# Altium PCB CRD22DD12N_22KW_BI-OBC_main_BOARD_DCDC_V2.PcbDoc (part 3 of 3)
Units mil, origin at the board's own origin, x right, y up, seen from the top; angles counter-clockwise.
Board outline 9308.07 x 7086.6 mil, 4 copper layers (TOP, GND02, POWER03, BOTTOM), stack 74.3 mil thick; 339 components, 177 nets, 874 pads, 199 vias.
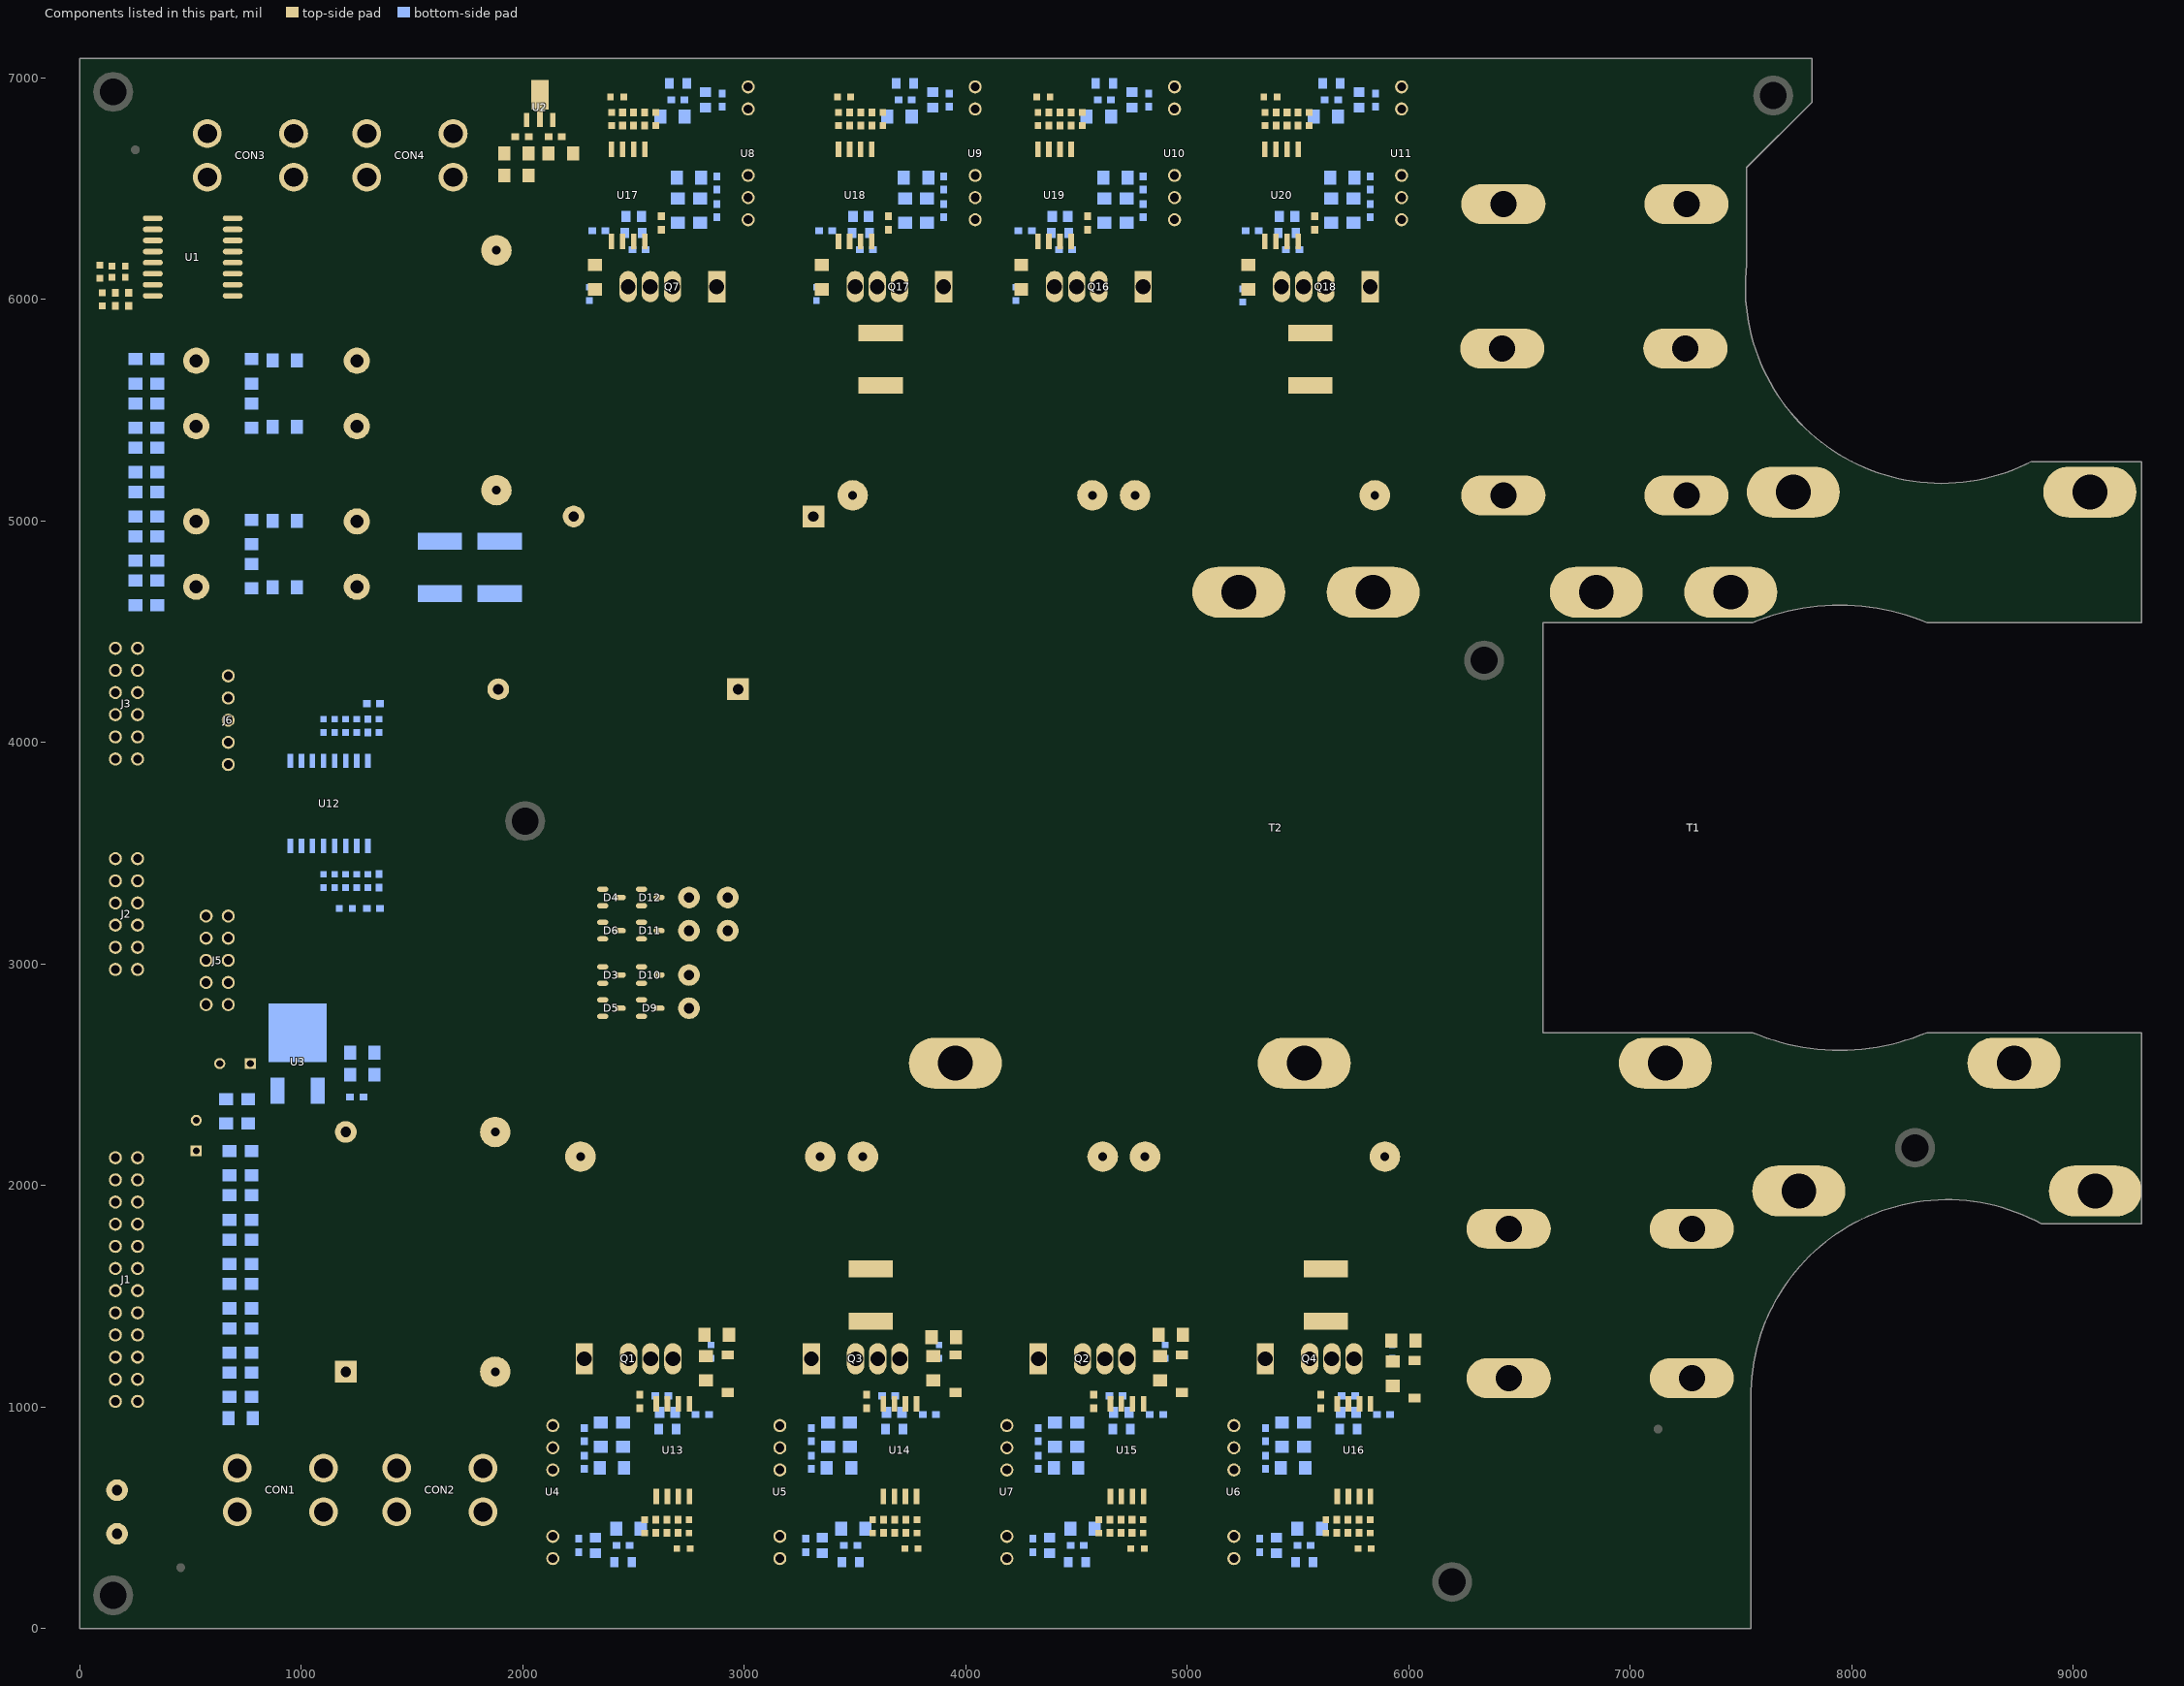
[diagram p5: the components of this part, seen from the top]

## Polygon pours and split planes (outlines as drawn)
DCINPUT on TOP "DCINPUT_L01_P003" (solid, pour order 3): 5960,2265 6035,2185 6032.5,2020 5885,1872.5 5885,1645 5830,1590 5345,1590 5220,1465 5135,1465 5080,1520 4765,1520 4710,1465 4425,1465 4395,1435 4395,1180 4345,1130 4250,1130 4220,1160 4220,1430 4140,1510 3860,1510 3780,1590 3350,1590 3225,1465 3080,1465 3010,1535 2730,1535 2660,1465 2395,1465 2345,1415 2345,1185 2300,1140 1985,1140 1795,950 1360,950 1200,790 1200,460 1185,445 655,445 635,465 635,765 695,825 695,1625 925,1855 2300,1855 2710,2265
VO+ on TOP "VO+_L01_P000" (solid, pour order 0): 1530,5516.28 1386.28,5660 470,5660 460,5670 460,5775 480,5795 600,5795 635,5830 635,5955 645,5965 725,5965 725,5985 645,5985 630,6000 630,6170 640,6180 1609.14,6180.86 1980,5810 2755,5810 2820,5875 2820,6130 2840,6150 2935,6150 2945,6140 2945,5900 3015,5830 3250,5830 3440,5640 3775,5640 3940,5805 4700,5805 4735,5840 4735,6135 4750,6150 4870,6150 4880,6140 4880,5880 4910,5850 5160,5850 5375,5635 5830,5635 5905,5560 5905,5060 5845,4997.5 5045,4995 4915,4865 3780,4870 1785,4865 1530,5120
SGND on GND02 "SGND_L02_P007" (solid, pour order 7): 6044.69,7005.25 6044.69,6714.69 5835,6505 5140,6505 5050,6595 5050,6634.74 4999.86,6684.88 4690.71,6684.88 4620,6614.17 4620,6565 4555,6500 4200,6500 4145,6555 4145,6633.28 4083.87,6694.41 3741.96,6694.41 3680,6632.46 3680,6540 3640,6500 3220,6500 3105,6615 2705,6615 2595,6505 2030,6505 2020,6515 2020,6857.62 1982.63,6894.99 442.54,6894.99 330,6782.46 330,4766 666.59,4429.41 1367.3,4429.41 1404.41,4392.3 1404.41,3757.7 1367.3,3720.59 50.47,3720.71 50.47,7036.01 6013.92,7036.01
AGND on GND02 "AGND_L02_P004" (solid, pour order 4): 52,3680 1366.72,3680 1404.41,3642.3 1404.41,2435.24 1290.67,2321.5 619.04,2321.5 355,2057.46 355,493.34 543.34,305 2007.46,305 2070,367.54 2070,490.89 2234.12,655 2475,655 2514.41,694.41 2514.41,759.41 2545,790 2975,790 3005,760 3005,641.98 3041.86,605.12 3458.19,605.12 3569.85,716.78 3569.85,754.85 3600,785 4076.27,785 4111.27,750 4111.27,691.42 4129.1,673.59 4538.59,673.59 4565,700 4565,750 4603.36,788.36 5006.64,788.36 5045,750 5045,602.54 5117.52,530.02 5482.72,530.02 5570,617.3 5570,760 5600,790 5940,790 5969.41,760.59 5969.41,69.42 5950,50 50,50 50,3677.99
PGND on GND02 "PGND_L02_P006" (solid, pour order 6): 628.41,2271.41 1306.04,2271.41 1354.04,2319.41 4979.41,2319.41 4980,2320 5160,2140 5675,2140 5969.95,1845.05 5969.95,855.05 5949.14,834.14 5555.86,834.14 5530,808.28 5530,634.11 5465.89,570 5125,570 5041.65,662.46 5041.65,1358.35 5020,1380 4820,1380 4790,1350 4235,1350 4215,1330 4215,1115 4102.5,1002.5 4102.5,852.5 4080,830 3580,830 3530,780 3530,734.11 3440.89,645 3058.61,645 3045.09,658.51 3045.09,808.19 3014.14,839.14 3014.14,1330.86 2960,1385 2730,1385 2685,1340 2180,1340 2125,1285 2125,1070 2030.59,975.59 2030.59,384.7 1990.89,345 555,345 395.03,504.97 395.03,2037.81 629.06,2271.85
SPGND on GND02 "SPGND_L02_P005" (solid, pour order 5): 774.83,5980 1210,6415.17 1210,6779.17 1235.83,6805 1236.41,6804.41 1905.59,6804.41 1950.59,6759.41 1950.59,6339.41 1951.41,6339.41 2360.83,5930 2361.14,5930.31 3105.31,5930.31 3217.5,6042.5 3217.5,6420 3242.5,6445 3731.91,6445 3772.5,6404.41 3772.5,5957.5 3799.41,5930.59 4880.59,5930.59 5150,6200 5150,6345 5255,6450 5600,6450 5700.41,6349.59 5700.41,5949.14 5770,5879.56 5770,5220.1 5514.32,4964.41 3609.41,4964.41 2880,4235 2881.75,4233.25 2881.75,4186.75 2881.24,4186.75 2869.49,4175 1600.83,4175 1515,4260.83 1515,4425 1470,4470 684,4470 370.59,4783.41 370.59,5870.59 480,5980
LEGB on POWER03 "LEGB_L03_P011" (solid, pour order 11): 4483.52,1143.35 4483.52,1753.52 4595,1865 4930,1865 4985,1920 5290,1920 5339.99,1870.01 6549.99,1870.01 6620,1800 6620,1100 6580.59,1060.59 6165.24,1060.59 6140,1085.83 6140,1284.17 6059.17,1365 5440.83,1365 5405,1329.17 5405,1140.83 5394.17,1130 5290,1130 5270.59,1149.41 5270.59,1278.9 5204.52,1344.97 4605.8,1344.97 4570,1309.17 4570,1150.83 4554.17,1135 4490.83,1135
DCINPUT on POWER03 "DCINPUT_L03_P010" (solid, pour order 10): 660.59,1315.59 1770,2425 3060,2425 3245,2240 4005,2240 4377.5,1867.5 4377.5,1145 4342.5,1110 4125,1110 4055,1180 4055,1350 4015,1390 2425,1390 2354.41,1319.41 2354.41,1147.41 2297,1090 1395,1090 1175,870 1175,510 1135,470 675.83,470 660,485.83 660,1314.17
SLEGA on POWER03 "SLEGA_L03_P009" (solid, pour order 9): 2724.17,6155 2735.59,6143.59 2735.59,5954.41 2835,5855 2975,5855 3080,5960 3270,5960 3375,5855 3755,5855 3825,5925 3825,6144.17 3840.83,6160 3974.17,6160 4000.59,6133.59 4000.59,5929.41 4075,5855 4875,5855 4975,5955 5195,5955 5295,5855 6015,5855 6240,6080 6240,6490 6285,6535 6544.56,6535 6585,6494.56 6585,5100 6535,5050 6270,5050 6035,5285 5425,5285 5340,5200 4955,5200 4870,5285 3390,5285 3300,5195 2815,5195 2635.59,5374.41 2635.59,6135.59 2654.41,6154.41
VO+ on POWER03 "VO+_L03_P008" (solid, pour order 8): 405,5775 457.5,5827.5 2080,5827.5 2165,5742.5 2165,5085 2070,4990 1475,4990 1365,5100 450,5100 405,5145
LEGA on BOTTOM "LEGA_L04_P014" (solid, pour order 14): 4200,2629.17 4159.17,2670 3125,2670 2690,2235 2690,1995 2430,1735 2430,1160.83 2445.83,1145 2499.17,1145 2515.59,1161.41 2515.59,1385.59 2625,1495 2880,1495 2910,1465 2980,1465 3137.49,1307.51 3137.49,1192.51 3204.41,1125.59 3325.59,1125.59 3350,1150 3350,1369.17 3498.33,1517.5 4142.5,1517.5 4200,1575
SLEGB on BOTTOM "SLEGB_L04_P013" (solid, pour order 13): 4220.59,5310.59 4490.2,5580.2 4490.2,5889.8 4560.59,5960.19 4560.59,6120.59 4579.41,6139.41 4640.59,6139.41 4655.59,6124.41 4655.59,5924.41 4753.15,5826.85 4896.47,5826.85 4952.12,5882.5 5089.17,5882.5 5196.09,5775.59 5665.59,5775.59 5755,5865 5755,6124.17 5770.47,6139.64 5940.32,6139.64 5959.88,6120.08 5959.88,5625.14 5610.59,5275.85 5610.59,4869.41 5660.19,4819.81 5995.02,4819.81 6029.88,4784.95 6029.88,4570.14 6009.74,4550 4655,4550 4220.01,4984.99 4220.01,5309.35
VO+ on BOTTOM "VO+_L04_P012" (solid, pour order 12): 485.83,5980 645,5980 790,6125 1025,6125 1170,5980 2050,5980 2260,5770 2610,5770 2660,5820 2766.42,5820 2819.64,5873.22 2819.64,6139.61 2839.61,6159.59 2954.59,6159.59 2970,6144.17 2970,5870.38 2985.31,5855.07 3189.93,5855.07 3270,5775 3540,5775 3635,5680 3635,4984.17 3105,4454.17 3105,4265 3010.59,4170.59 2534.41,4170.59 2435,4270 2435,4994.74 2030,4995 2030,4900 1510.59,4900 1510.59,5548.59 1399.17,5660 1095.83,5660 1075,5680.83 1075,5789.17 1064.17,5800 1015,5800 935,5880 715.83,5880 624.41,5788.59 624.41,5664.41 610.36,5650.36 429.68,5650.36 410.03,5670.01 410.03,5904.52
no net on Top Overlay (solid): 5812,1310 5287,1310 5287,1120 5812,1120
no net on Top Overlay (solid): 4787,1310 4262,1310 4262,1120 4787,1120
no net on Top Overlay (solid): 3762,1310 3237,1310 3237,1120 3762,1120
no net on Top Overlay (solid): 2737,1310 2212,1310 2212,1120 2737,1120
no net on Top Overlay (solid): 5365,5965 5890,5965 5890,6155 5365,6155
no net on Top Overlay (solid): 4340,5965 4865,5965 4865,6155 4340,6155
no net on Top Overlay (solid): 3440,5965 3965,5965 3965,6155 3440,6155
no net on Top Overlay (solid): 2415,5965 2940,5965 2940,6155 2415,6155

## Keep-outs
BOTTOM:
  region: 5220.99,5560 5219.04,5584.79 5213.23,5608.98 5203.71,5631.95 5190.72,5653.16 5174.57,5672.07 5155.66,5688.22 5134.45,5701.21 5111.48,5710.73 5087.29,5716.54 5062.5,5718.49 5037.71,5716.54 5013.52,5710.73 4990.55,5701.21 4983.47,5696.88 4969.34,5688.22 4950.43,5672.07 4934.28,5653.16 4921.29,5631.95 4911.77,5608.98 4905.96,5584.79 4904.01,5560 4905.96,5535.21 4911.77,5511.02 4921.29,5488.05 4934.28,5466.84 4950.43,5447.93 4969.34,5431.78 4983.47,5423.12 4990.55,5418.79 5013.52,5409.27 5037.71,5403.46 5062.5,5401.51 5087.29,5403.46 5111.48,5409.27 5134.45,5418.79 5155.66,5431.78 5174.57,5447.93 5190.72,5466.84 5203.71,5488.05 5213.23,5511.02 5219.04,5535.21 5220.99,5560
  region: 5197.99,1740 5196.04,1764.79 5190.23,1788.98 5180.71,1811.95 5167.72,1833.16 5151.57,1852.07 5132.66,1868.22 5111.45,1881.21 5088.48,1890.73 5064.29,1896.54 5039.5,1898.49 5014.71,1896.54 4990.52,1890.73 4967.55,1881.21 4960.47,1876.88 4946.34,1868.22 4927.43,1852.07 4911.28,1833.16 4898.29,1811.95 4888.77,1788.98 4882.96,1764.79 4881.01,1740 4882.96,1715.21 4888.77,1691.02 4898.29,1668.05 4911.28,1646.84 4927.43,1627.93 4946.34,1611.78 4960.47,1603.12 4967.55,1598.79 4990.52,1589.27 5014.71,1583.46 5039.5,1581.51 5064.29,1583.46 5088.48,1589.27 5111.45,1598.79 5132.66,1611.78 5151.57,1627.93 5167.72,1646.84 5180.71,1668.05 5190.23,1691.02 5196.04,1715.21 5197.99,1740
  region: 3147.99,1740 3146.04,1764.79 3140.23,1788.98 3130.71,1811.95 3117.72,1833.16 3101.57,1852.07 3082.66,1868.22 3061.45,1881.21 3038.48,1890.73 3014.29,1896.54 2989.5,1898.49 2964.71,1896.54 2940.52,1890.73 2917.55,1881.21 2910.47,1876.88 2896.34,1868.22 2877.43,1852.07 2861.28,1833.16 2848.29,1811.95 2838.77,1788.98 2832.96,1764.79 2831.01,1740 2832.96,1715.21 2838.77,1691.02 2848.29,1668.05 2861.28,1646.84 2877.43,1627.93 2896.34,1611.78 2910.47,1603.12 2917.55,1598.79 2940.52,1589.27 2964.71,1583.46 2989.5,1581.51 3014.29,1583.46 3038.48,1589.27 3061.45,1598.79 3082.66,1611.78 3101.57,1627.93 3117.72,1646.84 3130.71,1668.05 3140.23,1691.02 3146.04,1715.21 3147.99,1740
  region: 3345.99,5560 3344.04,5584.79 3338.23,5608.98 3328.71,5631.95 3315.72,5653.16 3299.57,5672.07 3280.66,5688.22 3259.45,5701.21 3236.48,5710.73 3212.29,5716.54 3187.5,5718.49 3162.71,5716.54 3138.52,5710.73 3115.55,5701.21 3108.47,5696.88 3094.34,5688.22 3075.43,5672.07 3059.28,5653.16 3046.29,5631.95 3036.77,5608.98 3030.96,5584.79 3029.01,5560 3030.96,5535.21 3036.77,5511.02 3046.29,5488.05 3059.28,5466.84 3075.43,5447.93 3094.34,5431.78 3108.47,5423.12 3115.55,5418.79 3138.52,5409.27 3162.71,5403.46 3187.5,5401.51 3212.29,5403.46 3236.48,5409.27 3259.45,5418.79 3280.66,5431.78 3299.57,5447.93 3315.72,5466.84 3328.71,5488.05 3338.23,5511.02 3344.04,5535.21 3345.99,5560

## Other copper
TOP:
  pour cut-out: 1981.91,2130 ccw(c2259.83,2130) 2259.83,1852.08 ccw(c2259.83,2130) 2537.75,2130 ccw(c2259.83,2130) 2259.83,2407.92 ccw(c2259.83,2130)
  pour cut-out: 2228.66,4824.9 cw(c2228.66,5020) 2033.56,5020 cw(c2228.66,5020) 2228.66,5215.1 cw(c2228.66,5020) 2423.76,5020 cw(c2228.66,5020)
  pour cut-out: 5180.94,1740 5179.2,1762.13 5174.01,1783.71 5165.52,1804.21 5153.92,1823.13 5139.51,1840.01 5122.63,1854.42 5103.71,1866.02 5083.21,1874.51 5061.63,1879.7 5039.5,1881.44 5012.51,1881.44 4995.79,1874.51 4975.29,1866.02 4968.98,1862.15 4956.37,1854.42 4939.49,1840.01 4925.08,1823.13 4913.48,1804.21 4904.99,1783.71 4899.8,1762.13 4898.06,1740 4899.8,1717.87 4904.99,1696.29 4913.48,1675.79 4925.08,1656.87 4939.49,1639.99 4956.37,1625.58 4968.98,1617.85 4975.29,1613.98 4995.79,1605.49 5017.37,1600.3 5039.5,1598.56 5061.63,1600.3 5083.21,1605.49 5103.71,1613.98 5122.63,1625.58 5139.51,1639.99 5153.92,1656.87 5165.52,1675.79 5174.01,1696.29 5179.2,1717.87
  pour cut-out: 3130.94,1740 3129.2,1762.13 3124.01,1783.71 3115.52,1804.21 3103.92,1823.13 3089.51,1840.01 3072.63,1854.42 3053.71,1866.02 3033.21,1874.51 3011.63,1879.7 2989.5,1881.44 2962.51,1881.44 2945.79,1874.51 2925.29,1866.02 2918.98,1862.15 2906.37,1854.42 2889.49,1840.01 2875.08,1823.13 2863.48,1804.21 2854.99,1783.71 2849.8,1762.13 2848.06,1740 2849.8,1717.87 2854.99,1696.29 2863.48,1675.79 2875.08,1656.87 2889.49,1639.99 2906.37,1625.58 2918.98,1617.85 2925.29,1613.98 2945.79,1605.49 2967.37,1600.3 2989.5,1598.56 3011.63,1600.3 3033.21,1605.49 3053.71,1613.98 3072.63,1625.58 3089.51,1639.99 3103.92,1656.87 3115.52,1675.79 3124.01,1696.29 3129.2,1717.87
  pour cut-out: 5203.94,5560 5202.2,5582.13 5197.01,5603.71 5188.52,5624.21 5176.92,5643.13 5162.51,5660.01 5145.63,5674.42 5126.71,5686.02 5106.21,5694.51 5084.63,5699.7 5062.5,5701.44 5035.51,5701.44 5018.79,5694.51 4998.29,5686.02 4991.98,5682.15 4979.37,5674.42 4962.49,5660.01 4948.08,5643.13 4936.48,5624.21 4927.99,5603.71 4922.8,5582.13 4921.06,5560 4922.8,5537.87 4927.99,5516.29 4936.48,5495.79 4948.08,5476.87 4962.49,5459.99 4979.37,5445.58 4991.98,5437.85 4998.29,5433.98 5018.79,5425.49 5040.37,5420.3 5062.5,5418.56 5084.63,5420.3 5106.21,5425.49 5126.71,5433.98 5145.63,5445.58 5162.51,5459.99 5176.92,5476.87 5188.52,5495.79 5197.01,5516.29 5202.2,5537.87
  pour cut-out: 4668.33,4906.78 4668.17,4906.85 4668,4906.9 4667.83,4906.93 4667.66,4906.96 4667.49,4906.96 4667.31,4906.95 4667.14,4906.93 4666.97,4906.89 4666.8,4906.84 4666.67,4906.78 4648.16,4899.27 4629.06,4893.39 4609.53,4889.2 4589.7,4886.73 4569.74,4886 4549.79,4887.01 4530,4889.76 4510.52,4894.22 4491.51,4900.36 4473.11,4908.13 4455.45,4917.48 4438.68,4928.33 4422.92,4940.61 4408.28,4954.21 4394.89,4969.03 4382.84,4984.96 4372.22,5001.89 4363.12,5019.67 4355.61,5038.18 4349.73,5057.28 4345.54,5076.81 4343.07,5096.64 4342.34,5116.6 4343.35,5136.55 4346.1,5156.34 4350.56,5175.82 4356.7,5194.83 4364.47,5213.23 4373.82,5230.89 4384.67,5247.66 4396.95,5263.42 4410.55,5278.06 4425.37,5291.45 4441.3,5303.5 4458.23,5314.12 4476.01,5323.22 4494.52,5330.73 4513.62,5336.61 4533.15,5340.8 4552.98,5343.27 4572.94,5344 4592.89,5342.99 4612.68,5340.24 4632.16,5335.78 4651.17,5329.64 4666.67,5323.22 4666.83,5323.15 4667,5323.1 4667.17,5323.07 4667.34,5323.04 4667.51,5323.04 4667.69,5323.05 4667.86,5323.07 4668.03,5323.11 4668.2,5323.16 4668.33,5323.22 4686.84,5330.73 4705.94,5336.61 4725.47,5340.8 4745.3,5343.27 4765.26,5344 4785.21,5342.99 4805,5340.24 4824.48,5335.78 4843.49,5329.64 4861.89,5321.87 4879.55,5312.52 4896.32,5301.67 4912.08,5289.39 4926.72,5275.79 4940.11,5260.97 4952.16,5245.04 4962.78,5228.11 4971.88,5210.33 4979.39,5191.82 4985.27,5172.72 4989.46,5153.19 4991.93,5133.36 4992.66,5113.4 4991.65,5093.45 4988.9,5073.66 4984.44,5054.18 4978.3,5035.17 4970.53,5016.77 4961.18,4999.11 4950.33,4982.34 4938.05,4966.58 4924.45,4951.94 4909.63,4938.55 4893.7,4926.5 4876.77,4915.88 4858.99,4906.78 4840.48,4899.27 4821.38,4893.39 4801.85,4889.2 4782.02,4886.73 4762.06,4886 4742.11,4887.01 4722.32,4889.76 4702.84,4894.22 4683.83,4900.36 4668.33,4906.78
  pour cut-out: 4713.67,2337.84 4732.15,2345.43 4751.22,2351.38 4770.74,2355.64 4790.55,2358.19 4810.51,2359 4830.47,2358.07 4850.27,2355.4 4869.76,2351.02 4888.8,2344.96 4907.23,2337.26 4924.92,2327.98 4941.74,2317.19 4957.55,2304.99 4972.24,2291.44 4985.7,2276.68 4997.81,2260.79 5008.49,2243.91 5017.67,2226.16 5025.26,2207.68 5031.21,2188.61 5035.47,2169.09 5038.02,2149.28 5038.83,2129.32 5037.9,2109.36 5035.23,2089.56 5030.85,2070.07 5024.79,2051.03 5017.09,2032.6 5007.81,2014.91 4997.02,1998.09 4984.82,1982.28 4971.27,1967.59 4956.51,1954.13 4940.62,1942.02 4923.74,1931.34 4905.99,1922.16 4887.51,1914.57 4868.44,1908.62 4848.92,1904.36 4829.11,1901.81 4809.15,1901 4789.19,1901.93 4769.39,1904.6 4749.9,1908.98 4730.86,1915.04 4713.67,1922.16 4695.19,1914.57 4676.12,1908.62 4656.6,1904.36 4636.79,1901.81 4616.83,1901 4596.87,1901.93 4577.07,1904.6 4557.58,1908.98 4538.54,1915.04 4520.11,1922.74 4502.42,1932.02 4485.6,1942.81 4469.79,1955.01 4455.1,1968.56 4441.64,1983.32 4429.53,1999.21 4418.85,2016.09 4409.67,2033.84 4402.08,2052.32 4396.13,2071.39 4391.87,2090.91 4389.32,2110.72 4388.51,2130.68 4389.44,2150.64 4392.11,2170.44 4396.49,2189.93 4402.55,2208.97 4410.25,2227.4 4419.53,2245.09 4430.32,2261.91 4442.52,2277.72 4456.07,2292.41 4470.83,2305.87 4486.72,2317.98 4503.6,2328.66 4521.35,2337.84 4539.83,2345.43 4558.9,2351.38 4578.42,2355.64 4598.23,2358.19 4618.19,2359 4638.15,2358.07 4657.95,2355.4 4677.44,2351.02 4696.48,2344.96 4713.67,2337.84
  pour cut-out: 4667.5,5322.84 4685.98,5330.43 4705.05,5336.38 4724.57,5340.64 4744.38,5343.19 4764.34,5344 4784.3,5343.07 4804.1,5340.4 4823.59,5336.02 4842.63,5329.96 4861.06,5322.26 4878.75,5312.98 4895.57,5302.19 4911.38,5289.99 4926.07,5276.44 4939.53,5261.68 4951.64,5245.79 4962.32,5228.91 4971.5,5211.16 4979.09,5192.68 4985.04,5173.61 4989.3,5154.09 4991.85,5134.28 4992.66,5114.32 4991.73,5094.36 4989.06,5074.56 4984.68,5055.07 4978.62,5036.03 4970.92,5017.6 4961.64,4999.91 4950.85,4983.09 4938.65,4967.28 4925.1,4952.59 4910.34,4939.13 4894.45,4927.02 4877.57,4916.34 4859.82,4907.16 4841.34,4899.57 4822.27,4893.62 4802.75,4889.36 4782.94,4886.81 4762.98,4886 4743.02,4886.93 4723.22,4889.6 4703.73,4893.98 4684.69,4900.04 4667.5,4907.16 4649.02,4899.57 4629.95,4893.62 4610.43,4889.36 4590.62,4886.81 4570.66,4886 4550.7,4886.93 4530.9,4889.6 4511.41,4893.98 4492.37,4900.04 4473.94,4907.74 4456.25,4917.02 4439.43,4927.81 4423.62,4940.01 4408.93,4953.56 4395.47,4968.32 4383.36,4984.21 4372.68,5001.09 4363.5,5018.84 4355.91,5037.32 4349.96,5056.39 4345.7,5075.91 4343.15,5095.72 4342.34,5115.68 4343.27,5135.64 4345.94,5155.44 4350.32,5174.93 4356.38,5193.97 4364.08,5212.4 4373.36,5230.09 4384.15,5246.91 4396.35,5262.72 4409.9,5277.41 4424.66,5290.87 4440.55,5302.98 4457.43,5313.66 4475.18,5322.84 4493.66,5330.43 4512.73,5336.38 4532.25,5340.64 4552.06,5343.19 4572.02,5344 4591.98,5343.07 4611.78,5340.4 4631.27,5336.02 4650.31,5329.96 4667.5,5322.84
  region net AGND: 2590,410.68 2815,410.68 2840,410.68 2860,430.68 2860,610.68 2845,625.68 2820,625.68 2695,625.68 2690,620.68 2690,570.68 2705,555.68 2785,555.68 2795,555.68 2820,530.68 2820,470.68 2795,445.68 2790,445.68 2590,445.68 2585,440.68 2585,415.68 2590,410.68
  region net SPGND: 1280,6845 1715,6845 1727.5,6832.5 1732.5,6832.5 1780,6785 1780,6465 1960,6285 1965,6280 1965,6205 1930,6170 1865,6170 1640,6395 1620,6395 1550,6395 1280,6395 1230,6445 1230,6795 1280,6845
  region net SLEGA: 6285,6535 6545,6535 6585,6495 6585,5100 6545,5060 6535,5050 6270,5050 6260,5060 6240,5080 6240,6490 6285,6535
  region net AGND: 255,6380 360,6380 370,6370 370,6260 365,6255 250,6255 205,6300 165,6300 160,6305 160,6360 180,6380 255,6380
  region net SGND: 2065,6865 2065,6775 2040,6750 2015,6750 2010,6745 2010,6700 2000,6690 2000,6525 2010,6515 2125,6515 2140,6530 2140,6705 2130,6715 2130,6750 2090,6790 2090,6865 2085,6870 2070,6870 2065,6865
  pour cut-out: 3328.94,5560 3327.2,5582.13 3322.01,5603.71 3313.52,5624.21 3301.92,5643.13 3287.51,5660.01 3270.63,5674.42 3251.71,5686.02 3231.21,5694.51 3209.63,5699.7 3187.5,5701.44 3160.51,5701.44 3143.79,5694.51 3123.29,5686.02 3116.98,5682.15 3104.37,5674.42 3087.49,5660.01 3073.08,5643.13 3061.48,5624.21 3052.99,5603.71 3047.8,5582.13 3046.06,5560 3047.8,5537.87 3052.99,5516.29 3061.48,5495.79 3073.08,5476.87 3087.49,5459.99 3104.37,5445.58 3116.98,5437.85 3123.29,5433.98 3143.79,5425.49 3165.37,5420.3 3187.5,5418.56 3209.63,5420.3 3231.21,5425.49 3251.71,5433.98 3270.63,5445.58 3287.51,5459.99 3301.92,5476.87 3313.52,5495.79 3322.01,5516.29 3327.2,5537.87
  pour cut-out: 4976.73,6959.25 4975.54,6968.26 4972.07,6976.65 4966.54,6983.86 4959.33,6989.39 4950.94,6992.86 4941.93,6994.05 4932.92,6992.86 4924.53,6989.39 4917.32,6983.86 4911.79,6976.65 4908.32,6968.26 4907.13,6959.25 4908.32,6950.24 4911.79,6941.85 4917.32,6934.64 4924.53,6929.11 4932.92,6925.64 4941.93,6924.45 4950.94,6925.64 4959.33,6929.11 4966.54,6934.64 4972.07,6941.85 4975.54,6950.24 4976.73,6959.25
  pour cut-out: 3051.73,6959.25 3050.54,6968.26 3047.07,6976.65 3041.54,6983.86 3034.33,6989.39 3025.94,6992.86 3016.93,6994.05 3007.92,6992.86 2999.53,6989.39 2992.32,6983.86 2986.79,6976.65 2983.32,6968.26 2982.13,6959.25 2983.32,6950.24 2986.79,6941.85 2992.32,6934.64 2999.53,6929.11 3007.92,6925.64 3016.93,6924.45 3025.94,6925.64 3034.33,6929.11 3041.54,6934.64 3047.07,6941.85 3050.54,6950.24 3051.73,6959.25
  pour cut-out: 4076.73,6959.25 4075.54,6968.26 4072.07,6976.65 4066.54,6983.86 4059.33,6989.39 4050.94,6992.86 4041.93,6994.05 4032.92,6992.86 4024.53,6989.39 4017.32,6983.86 4011.79,6976.65 4008.32,6968.26 4007.13,6959.25 4008.32,6950.24 4011.79,6941.85 4017.32,6934.64 4024.53,6929.11 4032.92,6925.64 4041.93,6924.45 4050.94,6925.64 4059.33,6929.11 4066.54,6934.64 4072.07,6941.85 4075.54,6950.24 4076.73,6959.25
  region net VS+15V: 3965,6890 3910,6945 3200,6945 3150,6895 2795,6895 2745,6945 2285,6945 2255,6915 2255,6630 2250,6625 2205,6625 2200,6630 2200,6690 2160,6730 2160,6750 2125,6785 2125,6840 2150,6865 2150,7010 2176.6,7036.6 5560,7036.6 5570,7026.6 5570,6945 5145,6945 5100,6900 4830,6900 4785,6945 4195,6945 4140,6890 4057.58,6890 4054.84,6891.25 4052,6892.25 4049.09,6893 4046.12,6893.5 4043.12,6893.73 4040.11,6893.7 4037.11,6893.41 4034.15,6892.86 4031.25,6892.06 4028.43,6891 4026.28,6890 3965,6890
  region net N18067595: 8535,2670 9195,2670 9258.07,2606.93 9258.07,1875 9225,1841.93 9225,1840 8885,1840 8822.5,1902.5 8822.5,2107.5 8500,2430 8500,2635 8535,2670
  region net N17988199: 7035,6535 7425,6535 7465,6495 7465,5893.28 7465,5425 7570,5320 7855,5320 7915,5260 7915,5075 7860.59,5020.59 7355.59,5020.59 7342.3,5020.59 7342.17,5020.47 7342.04,5020.36 7341.89,5020.27 7341.73,5020.19 7341.57,5020.12 7341.41,5020.07 7341.24,5020.03 7341.06,5020.01 7340.89,5020 7040,5020 6990,5070 6990,6490 7035,6535
  region net N16123922: 530,6860 995,6860 1015,6860 1035,6860 1065,6830 1065,6240 1030,6205 1010,6205 655,6205 640,6220 640,6250 637.5,6252.5 637.5,6377.5 645,6385 660,6400 725,6400 725,6415 660,6415 637.5,6437.5 620,6455 530,6455 510,6475 510,6840 530,6860
  region net SGND: 5257,6649.32 5242,6664.32 5242,6844.32 5262,6864.32 5512,6864.32 5517,6859.32 5517,6834.32 5512,6829.32 5312,6829.32 5287,6804.32 5280,6797.32 5280,6749.32 5310,6719.32 5317,6719.32 5397,6719.32 5412,6704.32 5412,6654.32 5407,6649.32 5257,6649.32
  region net PGND: 5500,1405 5500,1165 5515,1150 5580,1150 5600,1170 5600,1320 5620,1340 5725,1340 5735,1350 5735,1410 5720,1425 5520,1425 5500,1405
  region net SPGND: 3525,5835 3730,5835 3760,5865 3760,6150 3670,6150 3655,6135 3655,5960 3645,5950 3530,5950 3515,5935 3515,5845 3525,5835
  region net PGND: 3450,1400 3450,1160 3465,1145 3530,1145 3550,1165 3550,1315 3570,1335 3675,1335 3685,1345 3685,1405 3670,1420 3470,1420 3450,1400
  region net N17997979: 360,6075 285,6075 280,6075 165,6075 160,6080 160,6105 155,6110 70,6110 65,6105 65,6025 75,6015 230,6015 235,6010 245,6000 360,6000 370,6010 370,6065 360,6075
  region net N16148550: 1215,4940 390,4940 375,4955 375,5455 420,5500 1175,5500 1295,5500 1315,5480 1315,4965 1290,4940 1215,4940
  region net SGND: 3332,6649.32 3317,6664.32 3317,6844.32 3337,6864.32 3587,6864.32 3592,6859.32 3592,6834.32 3587,6829.32 3387,6829.32 3362,6804.32 3355,6797.32 3355,6749.32 3385,6719.32 3392,6719.32 3472,6719.32 3487,6704.32 3487,6654.32 3482,6649.32 3332,6649.32
  region net AGND: 5665,410.68 5890,410.68 5915,410.68 5935,430.68 5935,610.68 5920,625.68 5895,625.68 5770,625.68 5765,620.68 5765,570.68 5780,555.68 5860,555.68 5870,555.68 5895,530.68 5895,470.68 5870,445.68 5865,445.68 5665,445.68 5660,440.68 5660,415.68 5665,410.68
  region net SGND: 2562,6864.32 2567,6859.32 2567,6834.32 2562,6829.32 2365,6829.32 2350,6814.32 2345,6814.32 2325,6794.32 2325,6789.32 2325,6759.32 2350,6734.32 2445,6734.32 2465,6714.32 2465,6654.32 2455,6644.32 2290,6644.32 2278.5,6655.82 2278.5,6795.82 2347,6864.32 2562,6864.32
  region net AGND: 3619.17,410.68 3844.17,410.68 3869.17,410.68 3889.17,430.68 3889.17,610.68 3874.17,625.68 3849.17,625.68 3724.17,625.68 3719.17,625.68 3714.17,620.68 3714.17,570.68 3729.17,555.68 3734.17,555.68 3814.17,555.68 3824.17,555.68 3849.17,530.68 3849.17,470.68 3824.17,445.68 3819.17,445.68 3619.17,445.68 3614.17,440.68 3614.17,415.68 3619.17,410.68
  region net N17988090: 7515,1650 7515,1075 7480,1040 7124.06,1040 7109.06,1055 7080,1084.06 7080,2075 7125,2120 7155,2120 7930,2120 7970,2080 7970,1875 7910,1815 7824.06,1815 7540,1815 7515,1790 7515,1650
  region net SGND: 4232,6649.32 4217,6664.32 4217,6844.32 4237,6864.32 4487,6864.32 4492,6859.32 4492,6834.32 4487,6829.32 4287,6829.32 4262,6804.32 4255,6797.32 4255,6749.32 4285,6719.32 4292,6719.32 4372,6719.32 4387,6704.32 4387,6654.32 4382,6649.32 4232,6649.32
  region net SPGND: 5455,5830 5455,5920 5470,5935 5560,5935 5580,5955 5580,6135 5595,6150 5665,6150 5675,6140 5675,5850 5655,5830 5455,5830
  region net VS+5V: 1860,6510 1930,6510 1945,6525 1945,6685 1945,6690 1980,6725 1980,6760 1990,6770 2020,6770 2030,6780 2030,6835 2025,6840 1860,6840 1845,6825 1845,6525 1860,6510
  region net AGND: 465,135 1910,135 1950,95 2370,95 5940,95 5950,85 5950,50 475,50 460,65 460,130 465,135
  region net AGND: 4640,410.68 4865,410.68 4890,410.68 4910,430.68 4910,610.68 4895,625.68 4870,625.68 4745,625.68 4740,620.68 4740,570.68 4755,555.68 4835,555.68 4845,555.68 4870,530.68 4870,470.68 4845,445.68 4840,445.68 4640,445.68 4635,440.68 4635,415.68 4640,410.68
  region net LEGB: 6220,1050 6235,1035 6640,1035 6665,1060 6665,1820 6585,1900 6285,1900 6220,1835 6220,1050
  region net VP+15V: 166 vertices and 0 holes, not listed, extent 2535,185 5660,335
  region net N17988317: 8915,5260 9230,5260 9255,5235 9255,4865 9255,4595 9215,4555 8615,4555 8020,4555 7945,4555 7865,4555 7817,4555 6720,4555 6665,4555 6630,4590 6630,4780 6665,4815 7915,4815 8375,4815 8470,4815 8915,5260
GND02:
  drawing of 109 lines, arcs and shapes, not listed
POWER03:
  pour cut-out: 5203.94,5560 5202.2,5582.13 5197.01,5603.71 5188.52,5624.21 5176.92,5643.13 5162.51,5660.01 5145.63,5674.42 5126.71,5686.02 5106.21,5694.51 5084.63,5699.7 5062.5,5701.44 5040.37,5699.7 5018.79,5694.51 4998.29,5686.02 4991.98,5682.15 4979.37,5674.42 4962.49,5660.01 4948.08,5643.13 4936.48,5624.21 4927.99,5603.71 4922.8,5582.13 4921.06,5560 4922.8,5537.87 4927.99,5516.29 4936.48,5495.79 4948.08,5476.87 4962.49,5459.99 4979.37,5445.58 4991.98,5437.85 4998.29,5433.98 5018.79,5425.49 5040.37,5420.3 5062.5,5418.56 5084.63,5420.3 5106.21,5425.49 5126.71,5433.98 5145.63,5445.58 5162.51,5459.99 5176.92,5476.87 5188.52,5495.79 5197.01,5516.29 5202.2,5537.87 5203.94,5560
  pour cut-out: 3328.94,5560 3327.2,5582.13 3322.01,5603.71 3313.52,5624.21 3301.92,5643.13 3287.51,5660.01 3270.63,5674.42 3251.71,5686.02 3231.21,5694.51 3209.63,5699.7 3187.5,5701.44 3165.37,5699.7 3143.79,5694.51 3123.29,5686.02 3116.98,5682.15 3104.37,5674.42 3087.49,5660.01 3073.08,5643.13 3061.48,5624.21 3052.99,5603.71 3047.8,5582.13 3046.06,5560 3047.8,5537.87 3052.99,5516.29 3061.48,5495.79 3073.08,5476.87 3087.49,5459.99 3104.37,5445.58 3116.98,5437.85 3123.29,5433.98 3143.79,5425.49 3165.37,5420.3 3187.5,5418.56 3209.63,5420.3 3231.21,5425.49 3251.71,5433.98 3270.63,5445.58 3287.51,5459.99 3301.92,5476.87 3313.52,5495.79 3322.01,5516.29 3327.2,5537.87 3328.94,5560
  pour cut-out: 3130.94,1740 3129.2,1762.13 3124.01,1783.71 3115.52,1804.21 3103.92,1823.13 3089.51,1840.01 3072.63,1854.42 3053.71,1866.02 3033.21,1874.51 3011.63,1879.7 2989.5,1881.44 2967.37,1879.7 2945.79,1874.51 2925.29,1866.02 2918.98,1862.15 2906.37,1854.42 2889.49,1840.01 2875.08,1823.13 2863.48,1804.21 2854.99,1783.71 2849.8,1762.13 2848.06,1740 2849.8,1717.87 2854.99,1696.29 2863.48,1675.79 2875.08,1656.87 2889.49,1639.99 2906.37,1625.58 2918.98,1617.85 2925.29,1613.98 2945.79,1605.49 2967.37,1600.3 2989.5,1598.56 3011.63,1600.3 3033.21,1605.49 3053.71,1613.98 3072.63,1625.58 3089.51,1639.99 3103.92,1656.87 3115.52,1675.79 3124.01,1696.29 3129.2,1717.87 3130.94,1740
  pour cut-out: 1984.34,2241.34 1982.99,2258.44 1978.99,2275.13 1972.42,2290.98 1963.46,2305.61 1952.32,2318.66 1939.27,2329.8 1924.64,2338.76 1908.79,2345.33 1892.1,2349.33 1875,2350.68 1857.9,2349.33 1841.21,2345.33 1825.36,2338.76 1820.48,2335.77 1810.73,2329.8 1797.68,2318.66 1786.54,2305.61 1777.58,2290.98 1771.01,2275.13 1767.01,2258.44 1765.66,2241.34 1767.01,2224.24 1771.01,2207.55 1777.58,2191.7 1786.54,2177.07 1797.68,2164.02 1810.73,2152.88 1820.48,2146.91 1825.36,2143.92 1841.21,2137.35 1857.9,2133.35 1875,2132 1892.1,2133.35 1908.79,2137.35 1924.64,2143.92 1939.27,2152.88 1952.32,2164.02 1963.46,2177.07 1972.42,2191.7 1978.99,2207.55 1982.99,2224.24 1984.34,2241.34
  pour cut-out: 2369.17,2130 2367.82,2147.1 2363.82,2163.79 2357.25,2179.64 2348.29,2194.27 2337.15,2207.32 2324.1,2218.46 2309.47,2227.42 2293.62,2233.99 2276.93,2237.99 2259.83,2239.34 2242.73,2237.99 2226.04,2233.99 2210.19,2227.42 2205.31,2224.43 2195.56,2218.46 2182.51,2207.32 2171.37,2194.27 2162.41,2179.64 2155.84,2163.79 2151.84,2147.1 2150.49,2130 2151.84,2112.9 2155.84,2096.21 2162.41,2080.36 2171.37,2065.73 2182.51,2052.68 2195.56,2041.54 2205.31,2035.57 2210.19,2032.58 2226.04,2026.01 2242.73,2022.01 2259.83,2020.66 2276.93,2022.01 2293.62,2026.01 2309.47,2032.58 2324.1,2041.54 2337.15,2052.68 2348.29,2065.73 2357.25,2080.36 2363.82,2096.21 2367.82,2112.9 2369.17,2130
  pour cut-out: 1349.54,5427.36 1347.62,5446.78 1341.96,5465.45 1332.76,5482.66 1320.38,5497.74 1305.3,5510.12 1288.09,5519.32 1269.42,5524.98 1250,5526.9 1230.58,5524.98 1211.91,5519.32 1200.44,5513.19 1194.7,5510.12 1179.62,5497.74 1167.24,5482.66 1158.04,5465.45 1152.38,5446.78 1150.46,5427.36 1152.38,5407.94 1158.04,5389.27 1167.24,5372.06 1179.62,5356.98 1194.7,5344.6 1200.44,5341.53 1211.91,5335.4 1230.58,5329.74 1250,5327.82 1269.42,5329.74 1288.09,5335.4 1305.3,5344.6 1320.38,5356.98 1332.76,5372.06 1341.96,5389.27 1347.62,5407.94 1349.54,5427.36
  pour cut-out: 624.54,5427.36 622.62,5446.78 616.96,5465.45 607.76,5482.66 595.38,5497.74 580.3,5510.12 563.09,5519.32 544.42,5524.98 525,5526.9 505.58,5524.98 486.91,5519.32 475.44,5513.19 469.7,5510.12 454.62,5497.74 442.24,5482.66 433.04,5465.45 427.38,5446.78 425.46,5427.36 427.38,5407.94 433.04,5389.27 442.24,5372.06 454.62,5356.98 469.7,5344.6 475.44,5341.53 486.91,5335.4 505.58,5329.74 525,5327.82 544.42,5329.74 563.09,5335.4 580.3,5344.6 595.38,5356.98 607.76,5372.06 616.96,5389.27 622.62,5407.94 624.54,5427.36
  region net N17988317: 8915,5260 9230,5260 9255,5235 9255,4865 9255,4595 9215,4555 8615,4555 8020,4555 7945,4555 7865,4555 7817,4555 6720,4555 6665,4555 6630,4590 6630,4780 6665,4815 7915,4815 8375,4815 8470,4815 8915,5260
  region net N18067595: 8535,2670 9195,2670 9258.07,2606.93 9258.07,1875 9225,1841.93 9225,1840 8885,1840 8500,2225 8500,2635 8535,2670
  region net N17988199: 7035,6535 7425,6535 7465,6495 7465,5893.28 7465,5425 7570,5320 7855,5320 7915,5260 7915,5075 7860.59,5020.59 7355.59,5020.59 7342.3,5020.59 7342.17,5020.47 7342.04,5020.36 7341.89,5020.27 7341.73,5020.19 7341.57,5020.12 7341.41,5020.07 7341.24,5020.03 7341.06,5020.01 7340.89,5020 7040,5020 6990,5070 6990,6490 7035,6535
  region net N17988090: 7515,1650 7515,1075 7480,1040 7124.06,1040 7109.06,1055 7080,1084.06 7080,2075 7125,2120 7155,2120 7930,2120 7970,2080 7970,1875 7910,1815 7824.06,1815 7540,1815 7515,1790 7515,1650
  region net SLEGB: 6010.59,4545 5060.83,4545 5060.65,4545.01 5060.48,4545.03 5060.31,4545.07 5060.14,4545.12 5059.98,4545.19 5059.83,4545.27 5059.68,4545.36 5059.54,4545.47 5059.41,4545.59 5045.59,4559.41 5045.47,4559.54 5045.36,4559.68 5045.27,4559.83 5045.19,4559.98 5045.12,4560.14 5045.07,4560.31 5045.03,4560.48 5045.01,4560.65 5045,4560.83 5045,4785 5080,4820 5995.59,4820 6030.59,4785 6030.59,4565 6010.59,4545
  pour cut-out: 5180.94,1740 5179.2,1762.13 5174.01,1783.71 5165.52,1804.21 5153.92,1823.13 5139.51,1840.01 5122.63,1854.42 5103.71,1866.02 5083.21,1874.51 5061.63,1879.7 5039.5,1881.44 5017.37,1879.7 4995.79,1874.51 4975.29,1866.02 4968.98,1862.15 4956.37,1854.42 4939.49,1840.01 4925.08,1823.13 4913.48,1804.21 4904.99,1783.71 4899.8,1762.13 4898.06,1740 4899.8,1717.87 4904.99,1696.29 4913.48,1675.79 4925.08,1656.87 4939.49,1639.99 4956.37,1625.58 4968.98,1617.85 4975.29,1613.98 4995.79,1605.49 5017.37,1600.3 5039.5,1598.56 5061.63,1600.3 5083.21,1605.49 5103.71,1613.98 5122.63,1625.58 5139.51,1639.99 5153.92,1656.87 5165.52,1675.79 5174.01,1696.29 5179.2,1717.87 5180.94,1740
  pour cut-out: 294.8,1025 293.61,1034.01 290.14,1042.4 284.61,1049.61 277.4,1055.14 269.01,1058.61 260,1059.8 250.99,1058.61 242.6,1055.14 235.39,1049.61 229.86,1042.4 226.39,1034.01 225.2,1025 226.39,1015.99 229.86,1007.6 235.39,1000.39 242.6,994.86 250.99,991.39 260,990.2 269.01,991.39 277.4,994.86 284.61,1000.39 290.14,1007.6 293.61,1015.99 294.8,1025
  pour cut-out: 194.8,1125 193.61,1134.01 190.14,1142.4 184.61,1149.61 177.4,1155.14 169.01,1158.61 160,1159.8 150.99,1158.61 142.6,1155.14 135.39,1149.61 129.86,1142.4 126.39,1134.01 125.2,1125 126.39,1115.99 129.86,1107.6 135.39,1100.39 142.6,1094.86 150.99,1091.39 160,1090.2 169.01,1091.39 177.4,1094.86 184.61,1100.39 190.14,1107.6 193.61,1115.99 194.8,1125
  pour cut-out: 294.8,1225 293.61,1234.01 290.14,1242.4 284.61,1249.61 277.4,1255.14 269.01,1258.61 260,1259.8 250.99,1258.61 242.6,1255.14 235.39,1249.61 229.86,1242.4 226.39,1234.01 225.2,1225 226.39,1215.99 229.86,1207.6 235.39,1200.39 242.6,1194.86 250.99,1191.39 260,1190.2 269.01,1191.39 277.4,1194.86 284.61,1200.39 290.14,1207.6 293.61,1215.99 294.8,1225
  pour cut-out: 194.8,1225 193.61,1234.01 190.14,1242.4 184.61,1249.61 177.4,1255.14 169.01,1258.61 160,1259.8 150.99,1258.61 142.6,1255.14 135.39,1249.61 129.86,1242.4 126.39,1234.01 125.2,1225 126.39,1215.99 129.86,1207.6 135.39,1200.39 142.6,1194.86 150.99,1191.39 160,1190.2 169.01,1191.39 177.4,1194.86 184.61,1200.39 190.14,1207.6 193.61,1215.99 194.8,1225
  pour cut-out: 294.8,1125 293.61,1134.01 290.14,1142.4 284.61,1149.61 277.4,1155.14 269.01,1158.61 260,1159.8 250.99,1158.61 242.6,1155.14 235.39,1149.61 229.86,1142.4 226.39,1134.01 225.2,1125 226.39,1115.99 229.86,1107.6 235.39,1100.39 242.6,1094.86 250.99,1091.39 260,1090.2 269.01,1091.39 277.4,1094.86 284.61,1100.39 290.14,1107.6 293.61,1115.99 294.8,1125
  region net VP+5V: 550,2125 390,1965 390,1015 345,970 115,970 100,985 100,1260 110,1270 270,1270 305,1305 305,2020 465,2180 545,2180 550,2175 550,2125
BOTTOM:
  drawing of 78 lines, arcs and shapes, not listed

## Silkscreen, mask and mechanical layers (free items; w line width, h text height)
Top Overlay:
  drawing of 8908 lines, arcs and shapes, not listed
  text "CRD22DD12N_22KW_BI-OBC_MAIN_BOARD" at 6216,426.83 h35
  text "Rev B 1020" at 6216,366 h35
DESIGN_OUTLINE:
  lines w1: 8811.07,5267.93 9308.07,5267.93 9308.07,4540 8338.44,4540 ccw(c7945.5,3615.03) 7552.56,4540 6606,4540 6606,2690 7552.56,2690 ccw(c7945.5,3615) 8338.44,2690 9308.07,2690 9308.07,1826.55 8855.85,1826.55 ccw(c8430,1049.8) 7544.23,1039.59 7544.23,229.23 7544.23,0 0,0 0,7086.6 7820,7086.6 7820,6890 7525,6595 7525,6156.64 ccw(c8405,6055.2) 8811.07,5267.93
DFA_BOUND_TOP:
  region: 6255,3436.5 6455,3436.5 6455,3793.5 6255,3793.5
  region: 3095,3436.5 3295,3436.5 3295,3793.5 3095,3793.5
DFA_BOUND_BOTTOM:
  dashed: 5201.5,5421 5201.5,5699 4923.5,5699 4923.5,5421 5201.5,5421
  dashed: 3326.5,5421 3326.5,5699 3048.5,5699 3048.5,5421 3326.5,5421
  dashed: 5178.5,1601 5178.5,1879 4900.5,1879 4900.5,1601 5178.5,1601
  dashed: 3128.5,1601 3128.5,1879 2850.5,1879 2850.5,1601 3128.5,1601
PLACE_BOUND_TOP:
  drawing of 12 lines, arcs and shapes, not listed
PLACE_BOUND_BOTTOM:
  region: 5201.5,5421 5201.5,5699 4923.5,5699 4923.5,5421 5201.5,5421
  region: 3326.5,5421 3326.5,5699 3048.5,5699 3048.5,5421 3326.5,5421
  region: 5178.5,1601 5178.5,1879 4900.5,1879 4900.5,1601 5178.5,1601
  region: 3128.5,1601 3128.5,1879 2850.5,1879 2850.5,1601 3128.5,1601
  region: 7186,927.5 7186,872.5 7184.9,871.4 7152.5,839 7097.5,839 7096.15,840.35 7064,872.5 7064,927.5 7064.05,927.55 7097.5,961 7152.5,961 7186,927.5
  region: 516,302.5 516,247.5 514.9,246.4 482.5,214 427.5,214 426.15,215.35 394,247.5 394,302.5 394.05,302.55 427.5,336 482.5,336 516,302.5
  region: 311,6702.5 311,6647.5 309.9,6646.4 277.5,6614 222.5,6614 221.15,6615.35 189,6647.5 189,6702.5 189.05,6702.55 222.5,6736 277.5,6736 311,6702.5
PIN_NUMBER:
  text "1" at 140,6936.6 h25 r270
  text "1" at 7635,6920 h25 r270
  text "1" at 246,6675 h10
  text "1" at 246,6675 h10
  text "1" at 6330,4370 h25 r270
  text "1" at 2000,3645 h25 r270
  text "1" at 8275,2170 h25 r270
  text "1" at 7121,900 h10
  text "1" at 7121,900 h10
  text "1" at 451,275 h10
  text "1" at 451,275 h10
  text "1" at 6185,210 h25 r270
  text "1" at 140,150 h25 r270
ASSEMBLY_TOP:
  circle w2: c150,6936.6 r108.63
  circle w2: c7645,6920 r108.63
  circle w2: c6195,210 r108.63
  circle w2: c150,150 r108.63
  circle w2: c6340,4370 r108.63
  circle w2: c2010,3645 r108.63
  circle w2: c8285,2170 r108.63
  text "#DEV" at 84.4,6936.6 h31 r270
  text "#VAL" at 84.4,6936.6 h31 r270
  text "#TOL" at 84.4,6936.6 h31 r270
  text "HAMP" at 84.4,6936.6 h31 r270
  text "HAMP" at 7579.4,6920 h31 r270
  text "#TOL" at 7579.4,6920 h31 r270
  text "#VAL" at 7579.4,6920 h31 r270
  text "#DEV" at 7579.4,6920 h31 r270
  text "HAMP" at 200.4,6659 h31
  text "#TOL" at 200.4,6659 h31
  text "#VAL" at 200.4,6659 h31
  text "#DEV" at 200.4,6659 h31
  text "HAMP" at 6274.4,4370 h31 r270
  text "#TOL" at 6274.4,4370 h31 r270
  text "#VAL" at 6274.4,4370 h31 r270
  text "#DEV" at 6274.4,4370 h31 r270
  text "#DEV" at 1944.4,3645 h31 r270
  text "#VAL" at 1944.4,3645 h31 r270
  text "#TOL" at 1944.4,3645 h31 r270
  text "HAMP" at 1944.4,3645 h31 r270
  text "#DEV" at 3145.4,3599 h31
  text "#VAL" at 3145.4,3599 h31
  text "#TOL" at 3145.4,3599 h31
  text "HAMP" at 3145.4,3599 h31
  text "HAMP" at 6305.4,3599 h31
  text "#TOL" at 6305.4,3599 h31
  text "#VAL" at 6305.4,3599 h31
  text "#DEV" at 6305.4,3599 h31
  text "#DEV" at 8219.4,2170 h31 r270
  text "#VAL" at 8219.4,2170 h31 r270
  text "#TOL" at 8219.4,2170 h31 r270
  text "HAMP" at 8219.4,2170 h31 r270
  text "HAMP" at 7075.4,884 h31
  text "#TOL" at 7075.4,884 h31
  text "#VAL" at 7075.4,884 h31
  text "#DEV" at 7075.4,884 h31
  text "HAMP" at 405.4,259 h31
  text "#TOL" at 405.4,259 h31
  text "#VAL" at 405.4,259 h31
  text "#DEV" at 405.4,259 h31
  text "#DEV" at 6129.4,210 h31 r270
  text "#VAL" at 6129.4,210 h31 r270
  text "#TOL" at 6129.4,210 h31 r270
  text "HAMP" at 6129.4,210 h31 r270
  text "HAMP" at 84.4,150 h31 r270
  text "#TOL" at 84.4,150 h31 r270
  text "#VAL" at 84.4,150 h31 r270
  text "#DEV" at 84.4,150 h31 r270
ASSEMBLY_BOTTOM:
  text "HAMP" at 200.4,6659 h31
  text "#TOL" at 200.4,6659 h31
  text "#VAL" at 200.4,6659 h31
  text "#DEV" at 200.4,6659 h31
  text "#DEV" at 3137.9,5544 h31
  text "#VAL" at 3137.9,5544 h31
  text "#TOL" at 3137.9,5544 h31
  text "HAMP" at 3137.9,5544 h31
  text "HAMP" at 5012.9,5544 h31
  text "#TOL" at 5012.9,5544 h31
  text "#VAL" at 5012.9,5544 h31
  text "#DEV" at 5012.9,5544 h31
  text "HAMP" at 2939.9,1724 h31
  text "#TOL" at 2939.9,1724 h31
  text "#VAL" at 2939.9,1724 h31
  text "#DEV" at 2939.9,1724 h31
  text "#DEV" at 4989.9,1724 h31
  text "#VAL" at 4989.9,1724 h31
  text "#TOL" at 4989.9,1724 h31
  text "HAMP" at 4989.9,1724 h31
  text "HAMP" at 7075.4,884 h31
  text "#TOL" at 7075.4,884 h31
  text "#VAL" at 7075.4,884 h31
  text "#DEV" at 7075.4,884 h31
  text "HAMP" at 405.4,259 h31
  text "#TOL" at 405.4,259 h31
  text "#VAL" at 405.4,259 h31
  text "#DEV" at 405.4,259 h31
Mechanical 255:
  lines w1: 35,2815 145,2815 145,3235 35,3235 35,2815 ; 2235,1150 2235,1290 2320,1290 2320,1150 2235,1150 ; 2435,1150 2435,1290 2520,1290 2520,1150 2435,1150 ; 2630,5985 2630,6125 2715,6125 2715,5985 2630,5985 ; 3260,1145 3260,1285 3345,1285 3345,1145 3260,1145 ; 3460,1150 3460,1290 3545,1290 3545,1150 3460,1150 ; 3655,5985 3655,6125 3740,6125 3740,5985 3655,5985 ; 4485,1150 4485,1290 4570,1290 4570,1150 4485,1150 ; 4555,5985 4555,6125 4640,6125 4640,5985 4555,5985 ; 4760,5990 4760,6130 4845,6130 4845,5990 4760,5990 ; 5310,1150 5310,1290 5395,1290 5395,1150 5310,1150 ; 5510,1150 5510,1290 5595,1290 5595,1150 5510,1150 ; 5580,5985 5580,6125 5665,6125 5665,5985 5580,5985 ; 5785,5985 5785,6125 5870,6125 5870,5985 5785,5985
  lines w3: 130,150 170,150 ; 130,6936.6 170,6936.6 ; 150,130 150,170 ; 150,6916.6 150,6956.6 ; 1990,3645 2030,3645 ; 2010,3625 2010,3665 ; 2969.5,1740 3009.5,1740 ; 2989.5,1720 2989.5,1760 ; 3167.5,5560 3207.5,5560 ; 3175,3615 3215,3615 ; 3187.5,5540 3187.5,5580 ; 3195,3595 3195,3635 ; 5019.5,1740 5059.5,1740 ; 5039.5,1720 5039.5,1760 ; 5042.5,5560 5082.5,5560 ; 5062.5,5540 5062.5,5580 ; 6175,210 6215,210 ; 6195,190 6195,230 ; 6320,4370 6360,4370 ; 6335,3615 6375,3615 ; 6340,4350 6340,4390 ; 6355,3595 6355,3635 ; 7625,6920 7665,6920 ; 7645,6900 7645,6940 ; 8265,2170 8305,2170 ; 8285,2150 8285,2190 ; 230,6675 270,6675 230,6675 ; 250,6655 250,6695 250,6655 ; 435,275 475,275 435,275 ; 455,255 455,295 455,255 ; 7105,900 7145,900 7105,900 ; 7125,880 7125,920 7125,880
